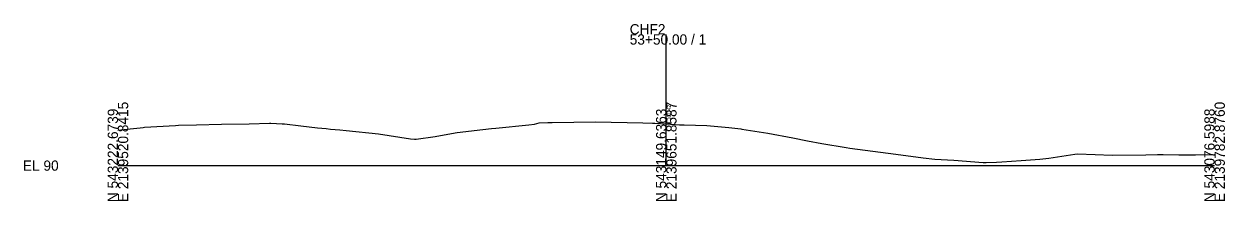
# Model space of a CAD drawing. Extents: x -12831 to 2303, y -10 to 39065.
# Drawn here: x 1974.3 to 2302.8, y 6990.3 to 7038.8 of the extents above; entities that cross this region are included whole.
import ezdxf

# ---------------------------------------------------------------- set-up
doc = ezdxf.new("R2010")
doc.units = 0
for name, color, linetype in [('RD_GPK_XS_Cell', 7, 'Continuous'), ('RD_XS_ExGround', 7, 'Continuous'), ('RD_XS_TX_Elev_EX', 7, 'Continuous')]:
    doc.layers.add(name, color=color, linetype=linetype)

msp = doc.modelspace()

# ---------------------------------------------------------------- linework, layer by layer
at = {"layer": 'RD_GPK_XS_Cell'}
for p, q in [((2150, 7000), (2150, 7035.94)), ((2000, 7000), (2150, 7000)), ((2150, 7000), (2300, 7000))]:
    msp.add_line(p, q, dxfattribs=at)
at = {"layer": 'RD_XS_ExGround'}
for p, q in [((2007.31, 7010.51), (2015.77, 7010.98)), ((2015.77, 7010.98), (2016.59, 7011.03)), ((2016.59, 7011.03), (2021.45, 7011.15)), ((2021.45, 7011.15), (2028.33, 7011.32)), ((2028.33, 7011.32), (2035.93, 7011.47)), ((2035.93, 7011.47), (2041.43, 7011.59)), ((2041.43, 7011.59), (2041.81, 7011.58)), ((2041.81, 7011.58), (2044.89, 7011.45)), ((2044.89, 7011.45), (2045.52, 7011.42)), ((2045.52, 7011.42), (2050.05, 7010.89)), ((2050.05, 7010.89), (2054.57, 7010.37)), ((2103.41, 7010.24), (2112.43, 7011.2)), ((2112.43, 7011.2), (2113.91, 7011.36)), ((2113.91, 7011.36), (2114.6, 7011.51)), ((2114.6, 7011.51), (2115.24, 7011.68)), ((2115.24, 7011.68), (2117.59, 7011.77)), ((2117.59, 7011.77), (2118.81, 7011.79)), ((2118.81, 7011.79), (2130.63, 7011.98)), ((2130.63, 7011.98), (2143.55, 7011.71)), ((2143.55, 7011.71), (2146.26, 7011.66)), ((2146.26, 7011.66), (2146.87, 7011.62)), ((2146.87, 7011.62), (2150, 7011.42)), ((2150, 7011.42), (2153.6, 7011.19)), ((2153.6, 7011.19), (2154.88, 7011.18)), ((2154.88, 7011.18), (2161.1, 7011)), ((2161.1, 7011), (2167.09, 7010.44)), ((2000, 7009.72), (2003.31, 7010.06)), ((2003.31, 7010.06), (2006.05, 7010.37)), ((2006.05, 7010.37), (2006.92, 7010.45)), ((2006.92, 7010.45), (2007.31, 7010.51)), ((2054.57, 7010.37), (2056.98, 7010.13)), ((2056.98, 7010.13), (2058.16, 7010.02)), ((2058.16, 7010.02), (2060.74, 7009.77)), ((2060.74, 7009.77), (2062.46, 7009.58)), ((2062.46, 7009.58), (2071.24, 7008.71)), ((2071.24, 7008.71), (2080.01, 7007.37)), ((2081.62, 7007.2), (2086.79, 7007.99)), ((2086.79, 7007.99), (2091.22, 7008.81)), ((2091.22, 7008.81), (2092.81, 7009.06)), ((2092.81, 7009.06), (2099.83, 7009.86)), ((2099.83, 7009.86), (2102.19, 7010.13)), ((2102.19, 7010.13), (2103.41, 7010.24)), ((2167.09, 7010.44), (2170.4, 7010.04)), ((2170.4, 7010.04), (2170.7, 7009.99)), ((2170.7, 7009.99), (2177.81, 7008.9)), ((2177.81, 7008.9), (2184.61, 7007.56)), ((2080.01, 7007.37), (2081.11, 7007.21)), ((2081.11, 7007.21), (2081.62, 7007.2)), ((2184.61, 7007.56), (2188.62, 7006.77)), ((2188.62, 7006.77), (2192.53, 7006.04)), ((2192.53, 7006.04), (2199.17, 7004.92)), ((2199.17, 7004.92), (2200.2, 7004.75)), ((2200.2, 7004.75), (2210.68, 7003.44)), ((2210.68, 7003.44), (2211.44, 7003.32)), ((2211.44, 7003.32), (2220.26, 7002.09)), ((2220.26, 7002.09), (2223.43, 7001.75)), ((2223.43, 7001.75), (2228.71, 7001.53)), ((2228.71, 7001.53), (2236.65, 7000.88)), ((2241.78, 7000.99), (2247.12, 7001.42)), ((2247.12, 7001.42), (2252.16, 7001.74)), ((2252.16, 7001.74), (2254.62, 7002.07)), ((2254.62, 7002.07), (2261.74, 7003.12)), ((2261.74, 7003.12), (2262.47, 7003.24)), ((2262.47, 7003.24), (2267.37, 7003.02)), ((2267.37, 7003.02), (2271.98, 7002.84)), ((2271.98, 7002.84), (2281.17, 7002.99)), ((2281.17, 7002.99), (2284.34, 7003.04)), ((2284.34, 7003.04), (2285.96, 7003.05)), ((2285.96, 7003.05), (2290.22, 7002.99)), ((2290.22, 7002.99), (2293.56, 7002.93)), ((2293.56, 7002.93), (2294.73, 7002.96)), ((2294.73, 7002.96), (2300, 7003.03)), ((2236.65, 7000.88), (2237.51, 7000.86)), ((2237.51, 7000.86), (2240.35, 7000.93)), ((2240.35, 7000.93), (2241.78, 7000.99))]:
    msp.add_line(p, q, dxfattribs=at)

# ---------------------------------------------------------------- texts
at = {"layer": 'RD_GPK_XS_Cell'}
for s, p in [('CHF2', (2140, 7035.94)), ('53+50.00 / 1', (2140, 7033.14)), ('EL 90', (1974, 6998.6))]:
    msp.add_text(s, height=2.8, dxfattribs=at).set_placement(p)
for s, p in [('N 543222.6739', (2000, 6990)), ('E 2139520.8415', (2002.8, 6990)), ('N 543149.6363', (2150, 6990)), ('E 2139651.8587', (2152.8, 6990)), ('N 543076.5988', (2300, 6990)), ('E 2139782.8760', (2302.8, 6990))]:
    msp.add_text(s, height=2.8, rotation=90, dxfattribs=at).set_placement(p)
at = {"layer": 'RD_XS_TX_Elev_EX'}
msp.add_text('101.42', height=1, rotation=90, dxfattribs=at).set_placement((2151.25, 7012.42))

doc.saveas('drawing.dxf')
